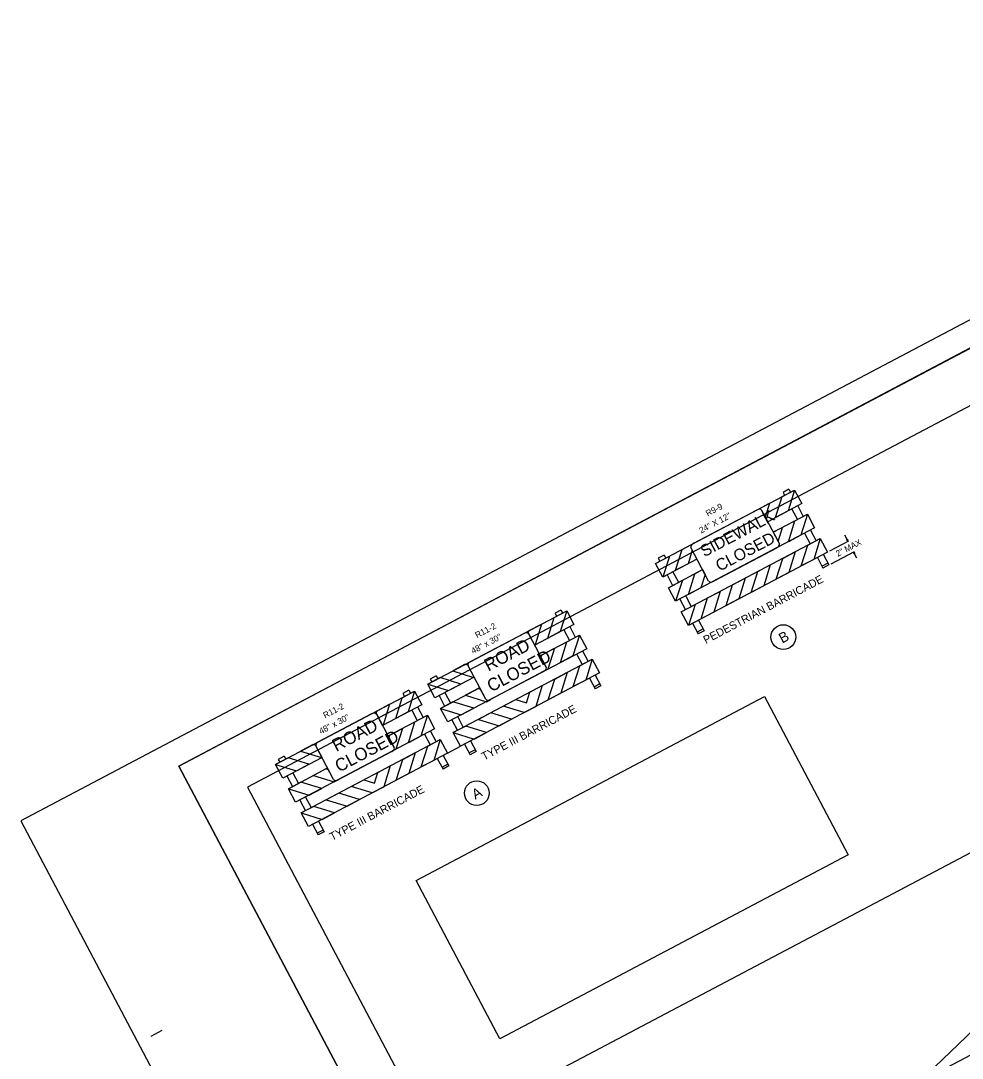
# Model space of a CAD drawing. Extents: x 1487052 to 1489663, y 496209 to 500965.
# Drawn here: x 1487338 to 1488265, y 498720 to 499742 of the extents above; entities that cross this region are included whole.
import ezdxf

# ---------------------------------------------------------------- set-up
doc = ezdxf.new("R2010")
doc.units = 0
for name, color, linetype in [('Default', 7, 'Continuous'), ('DEV BORDER CELL', 7, 'Continuous'), ('DEV DOT SWIRL SEAL CELL', 7, 'Continuous'), ('DEV TYPE 3 BARRICADE SINGLE WITH R11-2 CELL', 7, 'Continuous'), ('Gray Area Fill Shapes', 7, 'Continuous'), ('Scratch_Level_0', 7, 'Continuous'), ('Scratch_Level_2', 7, 'Continuous'), ('Scratch_Level_3', 7, 'Continuous'), ('Sheet Plot Border Outside CELL', 7, 'Continuous'), ('WZ OSDR CELL', 7, 'Continuous')]:
    doc.layers.add(name, color=color, linetype=linetype)

msp = doc.modelspace()

# ---------------------------------------------------------------- linework, layer by layer
at = {"layer": 'Default'}
for p, q in [((1487963.1, 499207.4), (1488100, 499279.7)), ((1488087.7, 499273.2), (1488100, 499279.7)), ((1488094.4, 499280.4), (1488088.6, 499277.4)), ((1488088.6, 499277.4), (1488090.1, 499274.5)), ((1488100, 499279.7), (1488093.6, 499259.2)), ((1488094.4, 499280.4), (1488095.9, 499277.5)), ((1488100, 499279.7), (1488107, 499266.3)), ((1488063, 499260.2), (1488075.3, 499266.7)), ((1488075.3, 499266.7), (1488071.1, 499253)), ((1488107, 499266.3), (1488073.5, 499248.5)), ((1488081.3, 499252.7), (1488087.7, 499273.2)), ((1488103, 499264.1), (1488108.5, 499253.7)), ((1488062.3, 499259.8), (1488063, 499260.2)), ((1488071.1, 499253), (1488067.5, 499259.9)), ((1488079, 499238.1), (1488112.6, 499255.8)), ((1488093.6, 499259.2), (1488081.3, 499252.7)), ((1488097.2, 499261), (1488102.7, 499250.6)), ((1488100.3, 499249.3), (1488112.6, 499255.8)), ((1488112.6, 499255.8), (1488106.2, 499235.3)), ((1488112.6, 499255.8), (1488119.7, 499242.4)), ((1488093.9, 499228.8), (1488100.3, 499249.3)), ((1488119.7, 499242.4), (1487982.8, 499170.1)), ((1488087.9, 499242.8), (1488079, 499238.1)), ((1488079, 499238.1), (1488083.7, 499229.1)), ((1488083.7, 499229.1), (1488087.9, 499242.8)), ((1488106.2, 499235.3), (1488093.9, 499228.8)), ((1488109.8, 499237.2), (1488115.3, 499226.7)), ((1488115.6, 499240.2), (1488121.1, 499229.8)), ((1488149.2, 499235.4), (1488152.5, 499229.2)), ((1487988.3, 499159.7), (1488125.2, 499231.9)), ((1487989.1, 499221.1), (1488001.4, 499227.6)), ((1487997.8, 499223.1), (1487999.2, 499220.4)), ((1488106.5, 499204.9), (1488112.9, 499225.4)), ((1488112.9, 499225.4), (1488125.2, 499231.9)), ((1488125.2, 499231.9), (1488118.8, 499211.4)), ((1488125.2, 499231.9), (1488132.3, 499218.5)), ((1488134.5, 499219.7), (1488153.4, 499229.7)), ((1488151.1, 499230.7), (1488152, 499231.2)), ((1487963.1, 499207.4), (1487976.8, 499214.6)), ((1487971.5, 499215.5), (1487965.7, 499212.5)), ((1487976.8, 499214.6), (1487970.2, 499194)), ((1487971.5, 499215.5), (1487973, 499212.6)), ((1487982.8, 499200.6), (1487989.1, 499221.1)), ((1487999.2, 499220.4), (1487995.1, 499207.1)), ((1488132.3, 499218.5), (1487995.4, 499146.3)), ((1488081.6, 499222.3), (1488069.3, 499215.8)), ((1488088.2, 499212.4), (1488100.5, 499218.9)), ((1488100.5, 499218.9), (1488094.2, 499198.4)), ((1488122.4, 499213.3), (1488127.9, 499202.8)), ((1488128.2, 499216.4), (1488133.7, 499205.9)), ((1488136, 499207.1), (1488158.9, 499219.2)), ((1488161.3, 499212.6), (1488158, 499218.7)), ((1488158.5, 499216.7), (1488159.4, 499217.2)), ((1487970.2, 499194), (1487963.1, 499207.4)), ((1487970.2, 499194), (1487963.1, 499207.4)), ((1487965.7, 499212.5), (1487967.2, 499209.6)), ((1488003.8, 499211.7), (1487970.2, 499194)), ((1487995.1, 499207.1), (1487982.8, 499200.6)), ((1488063.6, 499199.4), (1488075.9, 499205.9)), ((1488075.9, 499205.9), (1488069.6, 499185.4)), ((1488081.9, 499191.9), (1488088.2, 499212.4)), ((1488118.8, 499211.4), (1488106.5, 499204.9)), ((1488132.8, 499207.7), (1488127, 499204.6)), ((1488133.7, 499205.9), (1488127.9, 499202.8)), ((1487974.3, 499196.2), (1487979.8, 499185.7)), ((1487975.7, 499183.5), (1488009.3, 499201.3)), ((1487980.1, 499199.2), (1487985.6, 499188.8)), ((1487995.4, 499176.8), (1488001.7, 499197.3)), ((1488001.7, 499197.3), (1488009.3, 499201.3)), ((1488011.8, 499196.6), (1488007.7, 499183.3)), ((1488009.3, 499201.3), (1488011.8, 499196.6)), ((1488038.9, 499186.4), (1488051.2, 499192.9)), ((1488051.2, 499192.9), (1488044.9, 499172.4)), ((1488057.3, 499178.9), (1488063.6, 499199.4)), ((1488094.2, 499198.4), (1488081.9, 499191.9)), ((1487975.7, 499183.5), (1487989.4, 499190.8)), ((1487982.8, 499170.1), (1487975.7, 499183.5)), ((1487982.8, 499170.1), (1487975.7, 499183.5)), ((1487989.4, 499190.8), (1487982.8, 499170.1)), ((1488007.7, 499183.3), (1487995.4, 499176.8)), ((1488032.6, 499165.9), (1488038.9, 499186.4)), ((1488069.6, 499185.4), (1488057.3, 499178.9)), ((1487986.9, 499172.3), (1487992.4, 499161.8)), ((1487992.7, 499175.3), (1487998.2, 499164.9)), ((1488008, 499152.9), (1488014.3, 499173.4)), ((1488014.3, 499173.4), (1488026.6, 499179.9)), ((1488026.6, 499179.9), (1488020.3, 499159.4)), ((1488044.9, 499172.4), (1488032.6, 499165.9)), ((1487988.3, 499159.7), (1488002, 499166.9)), ((1488002, 499166.9), (1487995.4, 499146.3)), ((1487995.4, 499146.3), (1487988.3, 499159.7)), ((1487995.4, 499146.3), (1487988.3, 499159.7)), ((1488005.3, 499151.5), (1488010.8, 499141)), ((1488020.3, 499159.4), (1488008, 499152.9)), ((1487999.5, 499148.4), (1488005, 499138)), ((1488009.9, 499142.8), (1488004.1, 499139.7)), ((1488010.8, 499141), (1488005, 499138))]:
    msp.add_line(p, q, dxfattribs=at)
for points in [[(1488000.8, 499227.3), (1488062.3, 499259.8)], [(1488067.5, 499259.9), (1488085, 499226.7)], [(1488015.3, 499189.9), (1487997.8, 499223.1)], [(1488152, 499231.2), (1488152.5, 499229.2), (1488151.1, 499230.7)], [(1488082, 499222.5), (1488020.5, 499190)], [(1488158.5, 499216.7), (1488158, 499218.7), (1488159.4, 499217.2)]]:
    msp.add_lwpolyline(points, dxfattribs=at)
for points in [[(1488152, 499231.2), (1488151.1, 499230.7), (1488152.5, 499229.2)], [(1488158.5, 499216.7), (1488159.4, 499217.2), (1488158, 499218.7)]]:
    msp.add_lwpolyline(points, close=True, dxfattribs=at)
for centre, major_axis, start_param, end_param in [((1488063.4, 499257.8), (4.07, 2.15), 0, 1.570796), ((1488063.4, 499257.8), (4.07, 2.15), 0, 1.570796), ((1488001.8, 499225.3), (-4.07, -2.15), 4.556488, 6.283185), ((1488001.8, 499225.3), (-4.07, -2.15), 4.712162, 6.283185), ((1488080.9, 499224.5), (-4.07, -2.15), 1.570796, 3.141593), ((1488019.4, 499192), (-4.07, -2.15), 0, 1.570796)]:
    msp.add_ellipse(centre, major_axis=major_axis, ratio=0.5, start_param=start_param, end_param=end_param, dxfattribs=at)
at = {"layer": 'DEV BORDER CELL'}
for p, q in [((1487738.6, 499088.4), (1487875.5, 499160.7)), ((1487856.8, 499133.7), (1487863.2, 499154.2)), ((1487863.2, 499154.2), (1487875.5, 499160.7)), ((1487869.9, 499161.5), (1487864.1, 499158.4)), ((1487864.1, 499158.4), (1487865.6, 499155.5)), ((1487875.5, 499160.7), (1487869.1, 499140.2)), ((1487869.9, 499161.5), (1487871.4, 499158.6)), ((1487875.5, 499160.7), (1487882.5, 499147.3)), ((1487837.7, 499138.6), (1487838.5, 499141.2)), ((1487838.5, 499141.2), (1487850.8, 499147.7)), ((1487882.5, 499147.3), (1487844, 499126.9)), ((1487850.8, 499147.7), (1487844.5, 499127.2)), ((1487872.7, 499142.1), (1487878.2, 499131.6)), ((1487878.5, 499145.1), (1487884, 499134.7)), ((1487844, 499126.9), (1487838, 499138.2)), ((1487849.5, 499116.5), (1487888.1, 499136.8)), ((1487869.1, 499140.2), (1487856.8, 499133.7)), ((1487875.8, 499130.3), (1487888.1, 499136.8)), ((1487888.1, 499136.8), (1487881.7, 499116.3)), ((1487888.1, 499136.8), (1487895.2, 499123.4)), ((1487895.2, 499123.4), (1487758.3, 499051.2)), ((1487844.5, 499127.2), (1487844, 499126.9)), ((1487851.1, 499117.3), (1487863.4, 499123.8)), ((1487863.4, 499123.8), (1487857.1, 499103.3)), ((1487869.4, 499109.8), (1487875.8, 499130.3)), ((1487891.1, 499121.3), (1487896.6, 499110.8)), ((1487763.8, 499040.7), (1487900.7, 499113)), ((1487850.4, 499114.8), (1487851.1, 499117.3)), ((1487855.4, 499105.2), (1487850.4, 499114.8)), ((1487881.7, 499116.3), (1487869.4, 499109.8)), ((1487885.3, 499118.2), (1487890.8, 499107.7)), ((1487888.4, 499106.5), (1487900.7, 499113)), ((1487900.7, 499113), (1487894.3, 499092.5)), ((1487900.7, 499113), (1487907.8, 499099.5)), ((1487775.6, 499108), (1487763.3, 499101.5)), ((1487763.3, 499101.5), (1487783.8, 499095.1)), ((1487778.2, 499107.1), (1487775.6, 499108)), ((1487784.3, 499095.4), (1487778.4, 499106.6)), ((1487853.1, 499101.2), (1487800.4, 499073.4)), ((1487857.1, 499103.3), (1487853.1, 499101.2)), ((1487882, 499086), (1487888.4, 499106.5)), ((1487750.9, 499095), (1487738.6, 499088.4)), ((1487747, 499096.6), (1487741.2, 499093.5)), ((1487741.2, 499093.5), (1487742.7, 499090.6)), ((1487784.3, 499095.4), (1487745.7, 499075)), ((1487747, 499096.6), (1487748.5, 499093.7)), ((1487771.4, 499088.6), (1487750.9, 499095)), ((1487907.8, 499099.5), (1487770.9, 499027.3)), ((1487783.8, 499095.1), (1487784.3, 499095.4)), ((1487857.4, 499073), (1487863.7, 499093.5)), ((1487863.7, 499093.5), (1487876, 499100)), ((1487876, 499100), (1487869.7, 499079.5)), ((1487894.3, 499092.5), (1487882, 499086)), ((1487897.9, 499094.3), (1487903.4, 499083.9)), ((1487903.7, 499097.4), (1487909.2, 499086.9)), ((1487588.9, 499009.4), (1487725.7, 499081.6)), ((1487713.4, 499075.1), (1487725.7, 499081.6)), ((1487720.1, 499082.4), (1487714.3, 499079.3)), ((1487725.7, 499081.6), (1487719.4, 499061.1)), ((1487720.1, 499082.4), (1487721.7, 499079.5)), ((1487725.7, 499081.6), (1487732.8, 499068.2)), ((1487745.7, 499075), (1487738.6, 499088.4)), ((1487738.6, 499088.4), (1487759.1, 499082.1)), ((1487751.2, 499064.6), (1487789.8, 499085)), ((1487755.6, 499080.2), (1487761.1, 499069.8)), ((1487759.1, 499082.1), (1487771.4, 499088.6)), ((1487788.2, 499084.1), (1487775.9, 499077.6)), ((1487790.7, 499083.3), (1487788.2, 499084.1)), ((1487795.8, 499073.7), (1487790.7, 499083.3)), ((1487835.9, 499070), (1487839.1, 499080.5)), ((1487839.1, 499080.5), (1487851.4, 499087)), ((1487851.4, 499087), (1487845.1, 499066.5)), ((1487908.3, 499088.7), (1487902.5, 499085.6)), ((1487909.2, 499086.9), (1487903.4, 499083.9)), ((1487707.1, 499054.6), (1487713.4, 499075.1)), ((1487714.3, 499079.3), (1487715.8, 499076.4)), ((1487749.8, 499077.2), (1487755.3, 499066.7)), ((1487763.5, 499071.1), (1487751.2, 499064.6)), ((1487784, 499064.7), (1487763.5, 499071.1)), ((1487775.9, 499077.6), (1487796.4, 499071.2)), ((1487796.4, 499071.2), (1487800.4, 499073.4)), ((1487813.1, 499066.7), (1487825.4, 499073.2)), ((1487825.4, 499073.2), (1487835.9, 499070)), ((1487869.7, 499079.5), (1487857.4, 499073)), ((1487688, 499059.5), (1487688.8, 499062.1)), ((1487688.8, 499062.1), (1487701.1, 499068.6)), ((1487732.8, 499068.2), (1487694.2, 499047.8)), ((1487701.1, 499068.6), (1487694.8, 499048.1)), ((1487719.4, 499061.1), (1487707.1, 499054.6)), ((1487722.9, 499063), (1487728.4, 499052.5)), ((1487728.7, 499066.1), (1487734.3, 499055.6)), ((1487758.3, 499051.2), (1487751.2, 499064.6)), ((1487751.2, 499064.6), (1487771.7, 499058.2)), ((1487771.7, 499058.2), (1487784, 499064.7)), ((1487800.8, 499060.2), (1487788.5, 499053.7)), ((1487821.3, 499053.9), (1487800.8, 499060.2)), ((1487833.6, 499060.4), (1487813.1, 499066.7)), ((1487845.1, 499066.5), (1487832.8, 499060)), ((1487833.6, 499060.4), (1487845.9, 499066.9)), ((1487694.2, 499047.8), (1487688.3, 499059.1)), ((1487699.7, 499037.4), (1487738.3, 499057.8)), ((1487719.7, 499030.8), (1487726, 499051.3)), ((1487726, 499051.3), (1487738.3, 499057.8)), ((1487738.3, 499057.8), (1487732, 499037.3)), ((1487738.3, 499057.8), (1487745.4, 499044.3)), ((1487762.4, 499053.3), (1487767.9, 499042.9)), ((1487768.2, 499056.4), (1487773.7, 499045.9)), ((1487788.5, 499053.7), (1487809, 499047.4)), ((1487809, 499047.4), (1487821.3, 499053.9)), ((1487745.4, 499044.3), (1487608.6, 498972.1)), ((1487694.8, 499048.1), (1487694.2, 499047.8)), ((1487701.4, 499038.3), (1487713.7, 499044.8)), ((1487713.7, 499044.8), (1487707.4, 499024.3)), ((1487735.5, 499039.1), (1487741.1, 499028.7)), ((1487741.3, 499042.2), (1487746.9, 499031.7)), ((1487776.1, 499047.2), (1487763.8, 499040.7)), ((1487770.9, 499027.3), (1487763.8, 499040.7)), ((1487763.8, 499040.7), (1487784.3, 499034.4)), ((1487796.6, 499040.9), (1487776.1, 499047.2)), ((1487784.3, 499034.4), (1487796.6, 499040.9)), ((1487625.8, 499028.9), (1487613.5, 499022.4)), ((1487614.1, 498961.6), (1487750.9, 499033.9)), ((1487628.5, 499028.1), (1487625.8, 499028.9)), ((1487700.6, 499035.7), (1487701.4, 499038.3)), ((1487705.7, 499026.1), (1487700.6, 499035.7)), ((1487732, 499037.3), (1487719.7, 499030.8)), ((1487738.6, 499027.4), (1487750.9, 499033.9)), ((1487750.9, 499033.9), (1487744.6, 499013.4)), ((1487750.9, 499033.9), (1487758, 499020.5)), ((1487775, 499029.4), (1487780.5, 499019)), ((1487780.8, 499032.5), (1487786.3, 499022)), ((1487613.5, 499022.4), (1487634, 499016.1)), ((1487758, 499020.5), (1487621.2, 498948.2)), ((1487634.6, 499016.3), (1487628.6, 499027.6)), ((1487703.3, 499022.1), (1487650.6, 498994.3)), ((1487707.4, 499024.3), (1487703.4, 499022.1)), ((1487714, 499014.4), (1487726.3, 499020.9)), ((1487726.3, 499020.9), (1487720, 499000.4)), ((1487732.3, 499006.9), (1487738.6, 499027.4)), ((1487785.4, 499023.8), (1487779.6, 499020.7)), ((1487786.3, 499022), (1487780.5, 499019)), ((1487601.2, 499015.9), (1487588.9, 499009.4)), ((1487596, 498996), (1487588.9, 499009.4)), ((1487588.9, 499009.4), (1487609.4, 499003)), ((1487597.2, 499017.5), (1487591.4, 499014.4)), ((1487591.4, 499014.4), (1487592.9, 499011.5)), ((1487634.6, 499016.3), (1487596, 498996)), ((1487597.2, 499017.5), (1487598.8, 499014.6)), ((1487621.7, 499009.5), (1487601.2, 499015.9)), ((1487609.4, 499003), (1487621.7, 499009.5)), ((1487634, 499016.1), (1487634.6, 499016.3)), ((1487707.7, 498993.9), (1487714, 499014.4)), ((1487744.6, 499013.4), (1487732.3, 499006.9)), ((1487748.1, 499015.3), (1487753.7, 499004.8)), ((1487758.5, 499009.6), (1487752.7, 499006.5)), ((1487753.9, 499018.3), (1487759.5, 499007.9)), ((1487600, 498998.1), (1487605.6, 498987.7)), ((1487601.5, 498985.5), (1487640.1, 499005.9)), ((1487605.8, 499001.2), (1487611.4, 498990.7)), ((1487638.4, 499005), (1487626.1, 498998.5)), ((1487626.1, 498998.5), (1487646.6, 498992.2)), ((1487640.9, 499004.2), (1487638.4, 499005)), ((1487646, 498994.6), (1487640.9, 499004.2)), ((1487686.1, 498990.9), (1487689.4, 499001.4)), ((1487689.4, 499001.4), (1487701.7, 499007.9)), ((1487701.7, 499007.9), (1487695.3, 498987.4)), ((1487720, 499000.4), (1487707.7, 498993.9)), ((1487759.5, 499007.9), (1487753.7, 499004.8)), ((1487613.8, 498992), (1487601.5, 498985.5)), ((1487634.3, 498985.7), (1487613.8, 498992)), ((1487646.6, 498992.2), (1487650.6, 498994.3)), ((1487663.3, 498987.6), (1487675.7, 498994.1)), ((1487675.7, 498994.1), (1487686.1, 498990.9)), ((1487608.6, 498972.1), (1487601.5, 498985.5)), ((1487601.5, 498985.5), (1487622, 498979.2)), ((1487622, 498979.2), (1487634.3, 498985.7)), ((1487651, 498981.1), (1487638.7, 498974.6)), ((1487671.5, 498974.8), (1487651, 498981.1)), ((1487683.8, 498981.3), (1487663.3, 498987.6)), ((1487695.3, 498987.4), (1487683, 498980.9)), ((1487683.8, 498981.3), (1487696.2, 498987.8)), ((1487612.6, 498974.2), (1487618.2, 498963.8)), ((1487626.4, 498968.1), (1487614.1, 498961.6)), ((1487618.4, 498977.3), (1487624, 498966.9)), ((1487646.9, 498961.8), (1487626.4, 498968.1)), ((1487638.7, 498974.6), (1487659.2, 498968.3)), ((1487659.2, 498968.3), (1487671.5, 498974.8)), ((1487621.2, 498948.2), (1487614.1, 498961.6)), ((1487614.1, 498961.6), (1487634.6, 498955.3)), ((1487634.6, 498955.3), (1487646.9, 498961.8)), ((1487625.2, 498950.4), (1487630.8, 498939.9)), ((1487631, 498953.4), (1487636.6, 498943)), ((1487635.6, 498944.7), (1487629.8, 498941.7)), ((1487636.6, 498943), (1487630.8, 498939.9))]:
    msp.add_line(p, q, dxfattribs=at)
for points in [[(1487780.7, 499110.7), (1487833.4, 499138.5)], [(1487838, 499138.2), (1487855.4, 499105.2)], [(1487795.8, 499073.7), (1487778.4, 499106.6)], [(1487630.9, 499031.6), (1487683.6, 499059.4)], [(1487688.3, 499059.1), (1487705.7, 499026.1)], [(1487646, 498994.6), (1487628.6, 499027.6)]]:
    msp.add_lwpolyline(points, dxfattribs=at)
for centre, major_axis, start_param, end_param in [((1487834.5, 499136.3), (3.48, 1.84), 0, 1.570796), ((1487834.5, 499136.3), (3.48, 1.84), 6.283185, 6.491582), ((1487781.8, 499108.5), (-3.48, -1.84), 4.712162, 6.283185), ((1487781.8, 499108.5), (-3.48, -1.84), 6.074789, 6.283185), ((1487851.9, 499103.4), (-3.48, -1.84), 1.570796, 3.141593), ((1487851.9, 499103.4), (3.48, 1.84), 4.712389, 6.283185), ((1487799.2, 499075.5), (-3.48, -1.84), 0, 1.571024), ((1487799.2, 499075.5), (3.48, 1.84), 3.141593, 4.712389), ((1487684.8, 499057.2), (3.48, 1.84), 0, 1.570796), ((1487684.8, 499057.2), (3.48, 1.84), 6.283185, 6.491582), ((1487632.1, 499029.4), (-3.48, -1.84), 4.712162, 6.283185), ((1487632.1, 499029.4), (-3.48, -1.84), 6.074789, 6.283185), ((1487702.2, 499024.3), (-3.48, -1.84), 1.570796, 3.141593), ((1487702.2, 499024.3), (3.48, 1.84), 4.712389, 6.283185), ((1487649.5, 498996.5), (-3.48, -1.84), 0, 1.571024), ((1487649.5, 498996.5), (3.48, 1.84), 3.141593, 4.712389)]:
    msp.add_ellipse(centre, major_axis=major_axis, ratio=0.625, start_param=start_param, end_param=end_param, dxfattribs=at)
at = {"layer": 'DEV DOT SWIRL SEAL CELL'}
for centre in [(1488088.9, 499134.8), (1487787, 498981.1)]:
    msp.add_circle(centre, 12.2, dxfattribs=at)
at = {"layer": 'DEV TYPE 3 BARRICADE SINGLE WITH R11-2 CELL'}
msp.add_lwpolyline([(1488799.3, 499640.6), (1487561.2, 498986.9), (1488004.8, 498146.9), (1488782, 498557.2), (1488726.8, 498661.8), (1489187.6, 498905.1)], close=True, dxfattribs=at)
at = {"layer": 'Gray Area Fill Shapes'}
for centre in [(1488088.9, 499134.8), (1487787, 498981.1)]:
    msp.add_circle(centre, 12.2, dxfattribs=at)
at = {"layer": 'Scratch_Level_0'}
for p, q in [((1487494.6, 499008.3), (1487494.6, 499008.3)), ((1487494.6, 499008.3), (1487494.6, 499008.3)), ((1487466.3, 498741.7), (1487477.3, 498747.5))]:
    msp.add_line(p, q, dxfattribs=at)
msp.add_lwpolyline([(1488820.1, 499708.2), (1487493.7, 499007.8), (1487984, 498079.3), (1489310.4, 498779.7)], close=True, dxfattribs=at)
at = {"layer": 'Scratch_Level_2'}
for points in [[(1487727.3, 498895.1), (1488070.4, 499076.3), (1488152.8, 498920.3), (1487809.7, 498739.2)], [(1487796.6, 498670.7), (1488308.9, 498941.3), (1488391.2, 498785.3), (1487878.9, 498514.8)]]:
    msp.add_lwpolyline(points, close=True, dxfattribs=at)
at = {"layer": 'Scratch_Level_3'}
msp.add_lwpolyline([(1487493.7, 499007.8), (1488662.1, 499625.8), (1488820.1, 499708.2), (1489310.4, 498779.7), (1487984, 498079.3)], close=True, dxfattribs=at)
msp.add_lwpolyline([(1487493.7, 499007.8), (1488662.1, 499625.8), (1488820.1, 499708.2), (1489310.4, 498779.7), (1487984, 498079.3)], close=True, dxfattribs=at)
msp.add_lwpolyline([(1488617.1, 499075), (1488135, 498612.7), (1488123.4, 498651), (1488013.4, 498588.9), (1488016.8, 498549), (1487814.9, 498435.1), (1487860.6, 498348.6)], dxfattribs=at)
at = {"layer": 'Sheet Plot Border Outside CELL'}
msp.add_lwpolyline([(1487851.5, 497981.1), (1489344.2, 498769.3), (1488830.6, 499742), (1487337.9, 498953.8)], close=True, dxfattribs=at)
at = {"layer": 'WZ OSDR CELL'}
msp.add_line((1487758, 499020.5), (1487770.9, 499027.3), dxfattribs=at)

# ---------------------------------------------------------------- texts
at = {"layer": 'Default'}
for s, height, p in [('R9-9', 6, (1488014.4, 499253.5)), ("24'' X 12''", 6, (1488008, 499236.8)), ('SIDEWALK', 11.52, (1488011, 499213.4)), ('CLOSED', 11.52, (1488026, 499199.2)), ('2" MAX', 6, (1488142.5, 499213.8)), ('PEDESTRIAN BARRICADE', 7.882, (1488012.6, 499127.9))]:
    msp.add_text(s, height=height, rotation=27.8351, dxfattribs=at).set_placement(p)
at = {"layer": 'DEV BORDER CELL'}
for s, height, p in [('R11-2', 6, (1487787.3, 499133.6)), ("48'' x 30''", 6, (1487783.4, 499118.1)), ('ROAD', 12.37, (1487798.4, 499100.7)), ('CLOSED', 12.37, (1487801.2, 499080.3)), ('R11-2', 6, (1487637.6, 499054.6)), ('TYPE III BARRICADE', 7.882, (1487794.2, 499013.1)), ("48'' x 30''", 6, (1487633.6, 499039)), ('ROAD', 12.37, (1487648.6, 499021.6)), ('CLOSED', 12.37, (1487651.4, 499001.3)), ('TYPE III BARRICADE', 7.882, (1487644.5, 498934))]:
    msp.add_text(s, height=height, rotation=27.8351, dxfattribs=at).set_placement(p)
at = {"layer": 'DEV DOT SWIRL SEAL CELL'}
for s, p in [('B', (1488087.7, 499128.4)), ('A', (1487785.4, 498974.6))]:
    msp.add_text(s, height=10, rotation=27.8351, dxfattribs=at).set_placement(p)

doc.saveas('drawing.dxf')
